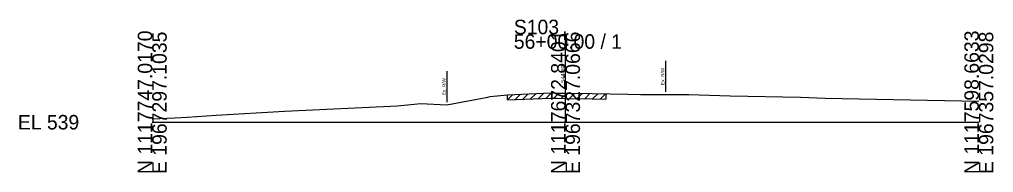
# Model space of a CAD drawing. Extents: x -26 to 163, y -10 to 24018.
# Drawn here: x -25.7 to 162.8, y 5490.3 to 5519.8 of the extents above; entities that cross this region are included whole.
import ezdxf

# ---------------------------------------------------------------- set-up
doc = ezdxf.new("R2010")
doc.units = 0
for name, color, linetype in [('RD_GPK_XS_Cell', 7, 'Continuous'), ('RD_XS_ExGround', 7, 'Continuous'), ('RD_XS_ExPaveRet', 7, 'Continuous'), ('RD_XS_ExRW', 7, 'Continuous'), ('RD_XS_TX_Elev_EX', 7, 'Continuous')]:
    doc.layers.add(name, color=color, linetype=linetype)

msp = doc.modelspace()

# ---------------------------------------------------------------- linework, layer by layer
at = {"layer": 'RD_GPK_XS_Cell'}
for p, q in [((80, 5500), (80, 5516.97)), ((0, 5500), (80, 5500)), ((80, 5500), (160, 5500))]:
    msp.add_line(p, q, dxfattribs=at)
at = {"layer": 'RD_XS_ExGround'}
msp.add_lwpolyline([(0, 5500.65), (4.37, 5500.85), (6.78, 5500.95), (12.38, 5501.34), (25.61, 5502.11), (47.45, 5503.14), (50.69, 5503.49), (51.92, 5503.62), (57.05, 5503.37), (64.99, 5504.83), (65.42, 5504.94), (68.75, 5505.31), (77.16, 5505.65), (77.5, 5505.66), (78.31, 5505.62), (80, 5505.59), (85.14, 5505.51), (92.08, 5505.38), (94.53, 5505.33), (95.01, 5505.34), (98.64, 5505.36), (103.86, 5505.33), (111.86, 5505.1), (125.49, 5504.81), (130.26, 5504.64), (160, 5504.07)], dxfattribs=at)
at = {"layer": 'RD_XS_ExPaveRet'}
for p, q in [((68.75, 5504.31), (69.79, 5505.35)), ((68.75, 5504.31), (68.75, 5505.31)), ((70.25, 5504.37), (71.29, 5505.41)), ((71.75, 5504.43), (72.79, 5505.47)), ((73.25, 5504.49), (74.29, 5505.53)), ((74.75, 5504.55), (75.79, 5505.59)), ((76.25, 5504.61), (77.29, 5505.65)), ((77.75, 5504.64), (78.72, 5505.61)), ((79.25, 5504.61), (80.23, 5505.59)), ((80.75, 5504.58), (81.73, 5505.57)), ((82.25, 5504.56), (83.23, 5505.54)), ((83.75, 5504.53), (84.73, 5505.52)), ((85.25, 5504.51), (86.23, 5505.49)), ((86.75, 5504.48), (87.73, 5505.46)), ((87.79, 5505.46), (87.79, 5504.46)), ((68.75, 5504.31), (77.16, 5504.65)), ((77.16, 5504.65), (77.5, 5504.66)), ((77.5, 5504.66), (78.31, 5504.62)), ((78.31, 5504.62), (80, 5504.59)), ((80, 5504.59), (85.14, 5504.51)), ((85.14, 5504.51), (87.79, 5504.46))]:
    msp.add_line(p, q, dxfattribs=at)
at = {"layer": 'RD_XS_ExRW'}
for p, q in [((99.38, 5511.86), (99.38, 5505.86)), ((57.05, 5509.87), (57.05, 5503.87))]:
    msp.add_line(p, q, dxfattribs=at)

# ---------------------------------------------------------------- texts
at = {"layer": 'RD_GPK_XS_Cell'}
for s, p in [('S103', (70, 5516.97)), ('56+00.00 / 1', (70, 5514.17)), ('EL 539', (-26, 5498.6))]:
    msp.add_text(s, height=2.8, dxfattribs=at).set_placement(p)
for s, p in [('N 1117747.0170', (0, 5490)), ('E 1967297.1035', (2.8, 5490)), ('N 1117672.8401', (80, 5490)), ('E 1967327.0666', (82.8, 5490)), ('N 1117598.6633', (160, 5490)), ('E 1967357.0298', (162.8, 5490))]:
    msp.add_text(s, height=2.8, rotation=90, dxfattribs=at).set_placement(p)
at = {"layer": 'RD_XS_ExRW'}
for p in [(99.13, 5507.2), (56.8, 5505.22)]:
    msp.add_text('Ex. R/W ', height=0.65, rotation=90, dxfattribs=at).set_placement(p)
at = {"layer": 'RD_XS_TX_Elev_EX'}
msp.add_text('544.59', height=0.8, rotation=90, dxfattribs=at).set_placement((79.9, 5507.59))

doc.saveas('drawing.dxf')
